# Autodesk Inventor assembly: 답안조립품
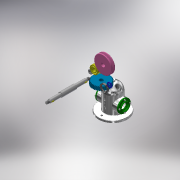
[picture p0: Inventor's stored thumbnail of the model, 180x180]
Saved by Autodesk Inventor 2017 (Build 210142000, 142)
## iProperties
Created: 2019-11
Part Number: 답안조립품
Document SubType Name: Assembly
Designer: 1-19-lg
Author: 1-19-lg
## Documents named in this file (14)
- C:\Users\1-19-lg\Desktop\491104V1003\답안조립품.iam
- C:\Users\1-19-lg\Desktop\491104V1003\본체.ipt
- C:\Users\1-19-lg\Desktop\491104V1003\부시.ipt
- C:\Users\1-19-lg\Desktop\491104V1003\스퍼기어.ipt
- C:\Users\1-19-lg\Desktop\491104V1003\오일 실 26 38 8.ipt
- C:\Users\1-19-lg\Desktop\491104V1003\와셔 12x24.ipt
- C:\Users\1-19-lg\Desktop\491104V1003\축.ipt
- C:\Users\1-19-lg\Desktop\491104V1003\커버.ipt
- C:\Users\1-19-lg\Desktop\491104V1003\키 5x5x12.ipt
- C:\Users\1-19-lg\Desktop\491104V1003\볼트 M4.ipt
- C:\Users\1-19-lg\Desktop\491104V1003\너트 M12x1.25.ipt
- C:\Users\1-19-lg\Desktop\491104V1003\베어링 6203.ipt
- C:\Users\1-19-lg\Desktop\491104V1003\V-벨트풀리.ipt
- V-벨트풀리.ipt
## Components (1 placed, 1 different names)
1. V-벨트풀리:1
